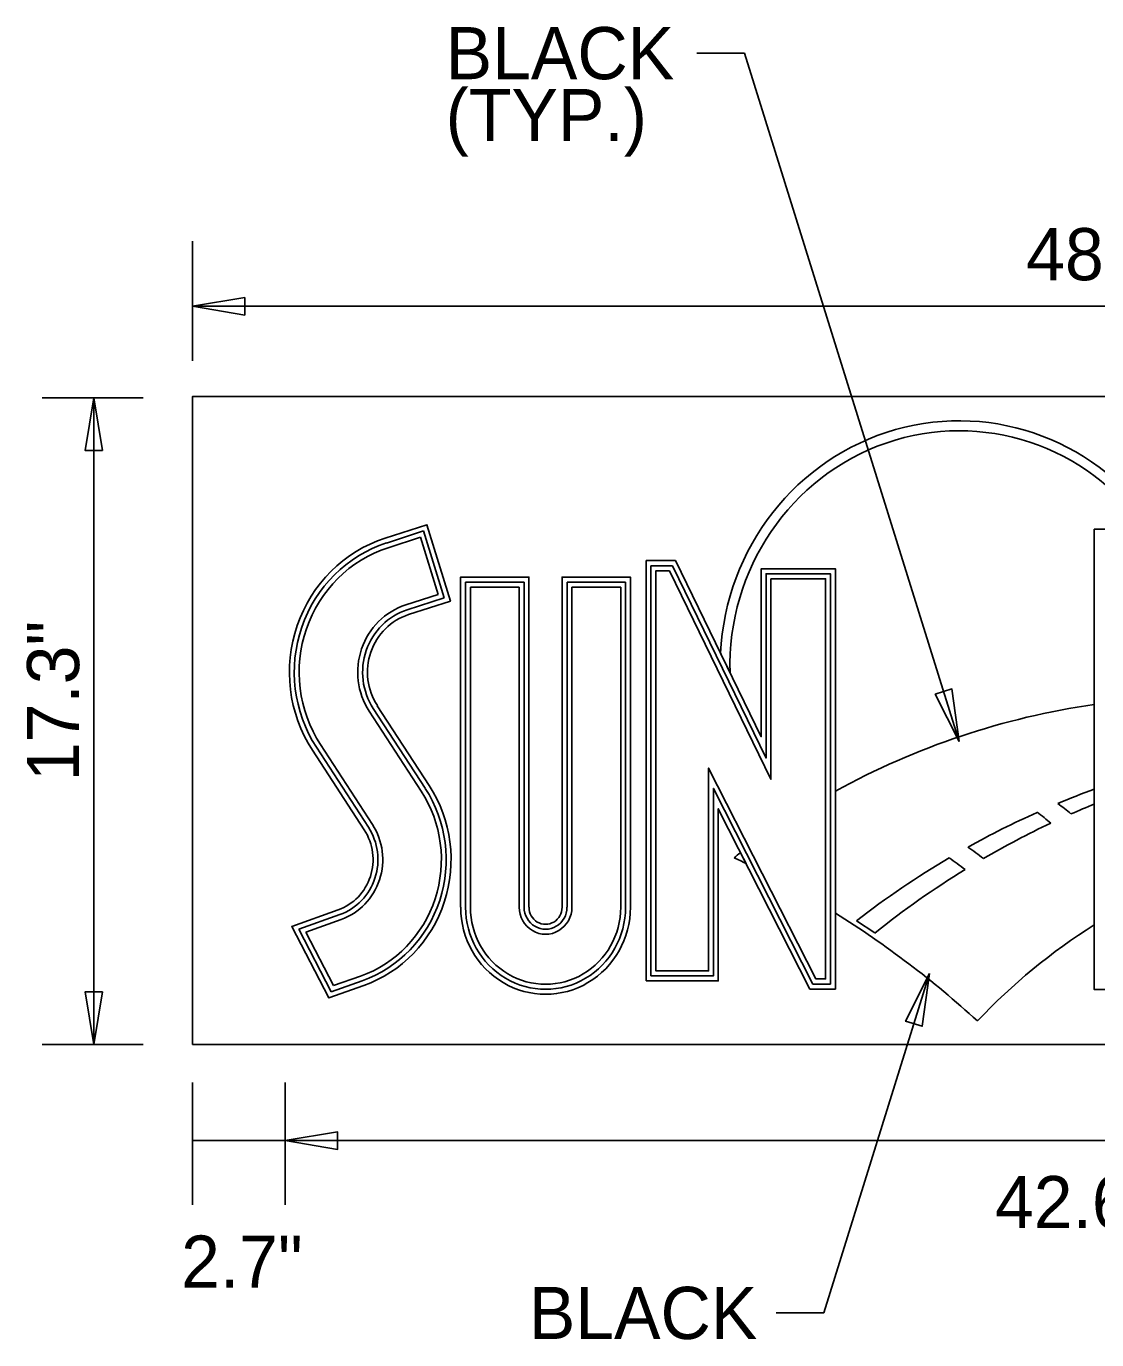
# Model space of a CAD drawing. Extents: x 10268197 to 10268738, y 2141503 to 2142677.
# Drawn here: x 10268673.67 to 10268688.05, y 2142371.53 to 2142389.16 of the extents above; entities that cross this region are included whole.
import ezdxf

# ---------------------------------------------------------------- set-up
doc = ezdxf.new("R2010")
doc.units = 0
for name, color, linetype in [('1', 7, 'Continuous'), ('Default', 7, 'Continuous'), ('GSDims', 7, 'Continuous')]:
    doc.layers.add(name, color=color, linetype=linetype)

msp = doc.modelspace()

# ---------------------------------------------------------------- linework, layer by layer
at = {"layer": '1'}
for p, q in [((10268682.678, 2142388.804), (10268683.317, 2142388.804)), ((10268686.203, 2142379.56), (10268683.317, 2142388.804)), ((10268685.804, 2142376.445), (10268684.382, 2142371.89)), ((10268699.488, 2142375.495), (10268675.901, 2142375.495)), ((10268683.743, 2142371.89), (10268684.382, 2142371.89))]:
    msp.add_line(p, q, dxfattribs=at)
at = {"layer": 'Default'}
for p, q in [((10268678.51, 2142382.227), (10268679.008, 2142382.389)), ((10268678.53, 2142382.163), (10268678.966, 2142382.304)), ((10268678.53, 2142382.163), (10268678.966, 2142382.304)), ((10268678.966, 2142382.304), (10268679.202, 2142381.536)), ((10268678.966, 2142382.304), (10268679.202, 2142381.536)), ((10268679.008, 2142382.389), (10268679.285, 2142381.492)), ((10268681.996, 2142381.99), (10268681.996, 2142376.347)), ((10268682.062, 2142376.414), (10268682.062, 2142381.922)), ((10268679.571, 2142377.336), (10268679.571, 2142381.703)), ((10268679.571, 2142381.703), (10268680.357, 2142381.703)), ((10268680.357, 2142381.703), (10268680.357, 2142377.337)), ((10268680.934, 2142377.337), (10268680.934, 2142381.703)), ((10268680.934, 2142381.703), (10268681.72, 2142381.703)), ((10268681.72, 2142381.703), (10268681.72, 2142377.336)), ((10268682.128, 2142381.855), (10268682.128, 2142376.481)), ((10268682.309, 2142381.855), (10268682.128, 2142381.855)), ((10268683.674, 2142379.056), (10268682.309, 2142381.855)), ((10268683.674, 2142381.748), (10268683.674, 2142379.056)), ((10268684.408, 2142381.748), (10268683.674, 2142381.748)), ((10268684.408, 2142376.374), (10268684.408, 2142381.748)), ((10268679.202, 2142381.536), (10268678.767, 2142381.395)), ((10268679.202, 2142381.536), (10268678.767, 2142381.395)), ((10268679.636, 2142377.337), (10268679.636, 2142381.636)), ((10268679.636, 2142381.636), (10268680.292, 2142381.636)), ((10268679.636, 2142377.337), (10268679.636, 2142381.636)), ((10268679.636, 2142381.636), (10268680.292, 2142381.636)), ((10268680.292, 2142381.636), (10268680.292, 2142377.337)), ((10268680.292, 2142381.636), (10268680.292, 2142377.337)), ((10268680.999, 2142377.337), (10268680.999, 2142381.636)), ((10268680.999, 2142381.636), (10268681.655, 2142381.636)), ((10268680.999, 2142377.337), (10268680.999, 2142381.636)), ((10268680.999, 2142381.636), (10268681.655, 2142381.636)), ((10268681.655, 2142381.636), (10268681.655, 2142377.337)), ((10268681.655, 2142381.636), (10268681.655, 2142377.337)), ((10268679.285, 2142381.492), (10268678.787, 2142381.331)), ((10268682.996, 2142380.747), (10268683.124, 2142380.484)), ((10268678.277, 2142379.969), (10268678.974, 2142378.896)), ((10268678.277, 2142379.969), (10268678.974, 2142378.896)), ((10268678.332, 2142380.006), (10268679.029, 2142378.934)), ((10268679.084, 2142378.971), (10268678.386, 2142380.043)), ((10268688.017, 2142378.923), (10268688.017, 2142380.059)), ((10268677.514, 2142379.447), (10268678.211, 2142378.375)), ((10268678.266, 2142378.412), (10268677.568, 2142379.484)), ((10268678.32, 2142378.449), (10268677.623, 2142379.521)), ((10268678.32, 2142378.449), (10268677.623, 2142379.521)), ((10268682.835, 2142376.481), (10268682.835, 2142379.205)), ((10268682.835, 2142379.205), (10268684.278, 2142376.374)), ((10268684.539, 2142378.896), (10268684.539, 2142377.259)), ((10268688.017, 2142377.099), (10268688.017, 2142378.722)), ((10268683.34, 2142377.925), (10268683.266, 2142378.069)), ((10268677.331, 2142377.042), (10268677.881, 2142377.238)), ((10268677.425, 2142377.004), (10268677.902, 2142377.174)), ((10268677.425, 2142377.004), (10268677.902, 2142377.174)), ((10268685.07, 2142376.991), (10268684.823, 2142377.156)), ((10268677.768, 2142376.202), (10268677.331, 2142377.042)), ((10268677.799, 2142376.284), (10268677.425, 2142377.004)), ((10268677.799, 2142376.284), (10268677.425, 2142377.004)), ((10268678.161, 2142376.413), (10268677.799, 2142376.284)), ((10268678.161, 2142376.413), (10268677.799, 2142376.284)), ((10268682.128, 2142376.481), (10268682.835, 2142376.481)), ((10268678.182, 2142376.349), (10268677.768, 2142376.202)), ((10268684.278, 2142376.374), (10268684.408, 2142376.374)), ((10268699.488, 2142375.495), (10268675.901, 2142375.495))]:
    msp.add_line(p, q, dxfattribs=at)
for points in [[(10268675.901, 2142375.495), (10268675.901, 2142384.193), (10268699.488, 2142384.193), (10268699.488, 2142375.495)], [(10268678.806, 2142381.267), (10268679.367, 2142381.448), (10268679.051, 2142382.473), (10268678.491, 2142382.292)], [(10268689.118, 2142382.412), (10268688.017, 2142382.412), (10268688.017, 2142376.232), (10268689.118, 2142376.232), (10268689.118, 2142378.639)], [(10268681.996, 2142376.347), (10268682.966, 2142376.347), (10268682.966, 2142378.658), (10268684.198, 2142376.239), (10268684.539, 2142376.239), (10268684.539, 2142381.882), (10268683.543, 2142381.882), (10268683.543, 2142379.625), (10268682.39, 2142381.99), (10268681.996, 2142381.99)], [(10268682.062, 2142381.922), (10268682.349, 2142381.922), (10268683.608, 2142379.34), (10268683.608, 2142381.815), (10268684.473, 2142381.815), (10268684.473, 2142376.306), (10268684.238, 2142376.306), (10268682.901, 2142378.931), (10268682.901, 2142376.414), (10268682.062, 2142376.414)], [(10268680.423, 2142377.337), (10268680.423, 2142381.77), (10268679.505, 2142381.77), (10268679.505, 2142377.337)], [(10268681.786, 2142377.337), (10268681.786, 2142381.77), (10268680.868, 2142381.77), (10268680.868, 2142377.337)], [(10268677.859, 2142377.301), (10268677.237, 2142377.079), (10268677.736, 2142376.119), (10268678.204, 2142376.286)]]:
    msp.add_lwpolyline(points, dxfattribs=at)
msp.add_lwpolyline([(10268683.674, 2142381.748), (10268683.674, 2142379.056), (10268682.309, 2142381.855), (10268682.128, 2142381.855), (10268682.128, 2142376.481), (10268682.835, 2142376.481), (10268682.835, 2142379.205), (10268684.278, 2142376.374), (10268684.408, 2142376.374), (10268684.408, 2142381.748)], close=True, dxfattribs=at)
for centre, major_axis, ratio, start_param, end_param in [((10268686.203, 2142380.578), (0, 3.29), 0.97582, 5.303349, 7.802858), ((10268686.203, 2142380.578), (0, 3.29), 0.97582, 5.303349, 7.802858), ((10268686.203, 2142380.578), (0, 3.156), 0.97582, 5.332201, 7.884008), ((10268686.203, 2142380.578), (0, 3.156), 0.97582, 5.332201, 7.884008), ((10268679.045, 2142380.493), (0, 1.886), 0.97582, 0.306207, 2.15869), ((10268679.045, 2142380.493), (0, 1.819), 0.97582, 0.306207, 2.15869), ((10268679.045, 2142380.493), (0, 1.752), 0.975477, 0.305879, 2.158799), ((10268679.045, 2142380.493), (0, 1.752), 0.975477, 0.305879, 2.158799), ((10268679.045, 2142380.493), (0, 0.946), 0.975477, 0.305879, 2.158799), ((10268679.045, 2142380.493), (0, 0.946), 0.975477, 0.305879, 2.158799), ((10268679.045, 2142380.493), (0, 0.878), 0.97582, 0.306207, 2.15869), ((10268679.045, 2142380.493), (0, 0.811), 0.97582, 0.306207, 2.15869), ((10268686.203, 2142380.577), (0, -3.156), 0.97582, 4.712389, 4.712389), ((10268689.453, 2142369.502), (0, 10.658), 0.97582, 0.138501, 0.492135), ((10268689.453, 2142369.502), (0, 10.658), 0.97582, 0.138501, 0.492135), ((10268677.63, 2142377.977), (0, -1.657), 0.975477, 0.334737, 2.158799), ((10268677.63, 2142377.977), (0, -1.657), 0.975477, 0.334737, 2.158799), ((10268677.629, 2142377.977), (0, 1.724), 0.97582, 3.476656, 5.300276), ((10268677.629, 2142377.977), (0, 1.791), 0.97582, 3.476656, 5.300276), ((10268692.076, 2142367.544), (0, -12.098), 0.987081, 3.48834, 3.532255), ((10268677.555, 2142365.833), (0, 16.388), 0.986504, 5.604488, 5.618403), ((10268692.471, 2142367.497), (0, -12.098), 0.987081, 3.5238, 3.552221), ((10268692.076, 2142367.544), (0, -12.098), 0.987081, 3.557551, 3.644446), ((10268677.555, 2142365.833), (0, 16.12), 0.986688, 5.613012, 5.627647), ((10268677.63, 2142377.977), (0, 0.716), 0.97582, 3.476661, 5.300276), ((10268677.63, 2142377.977), (0, 0.783), 0.97582, 3.476661, 5.300276), ((10268677.63, 2142377.977), (0, -0.85), 0.975477, 0.334742, 2.158799), ((10268677.63, 2142377.977), (0, -0.85), 0.975477, 0.334742, 2.158799), ((10268692.471, 2142367.497), (0, -12.098), 0.987081, 3.577057, 3.66248), ((10268689.453, 2142369.502), (0, 10.658), 0.97582, 0.637151, 0.647654), ((10268689.453, 2142369.502), (0, 10.658), 0.97582, 0.637152, 0.647654), ((10268677.61, 2142365.619), (0, 13.634), 0.97582, 5.837989, 5.851358), ((10268677.61, 2142365.619), (0, 13.634), 0.97582, 5.837989, 5.851358), ((10268692.076, 2142367.544), (0, -12.098), 0.987081, 3.668845, 3.794286), ((10268677.555, 2142365.833), (0, 14.911), 0.987597, 5.648885, 5.666846), ((10268677.555, 2142365.833), (0, 15.179), 0.987382, 5.641271, 5.658477), ((10268692.471, 2142367.497), (0, -12.098), 0.987081, 3.686493, 3.810103), ((10268680.646, 2142377.336), (0, 1.168), 0.97582, 1.570446, 4.71274), ((10268680.646, 2142377.336), (0, 1.101), 0.97582, 1.570446, 4.71274), ((10268680.646, 2142377.337), (0, -1.035), 0.975477, 4.712389, 7.853982), ((10268680.646, 2142377.337), (0, -1.035), 0.975477, 4.712389, 7.853982), ((10268680.646, 2142377.337), (0, -0.363), 0.975477, 4.712389, 7.853982), ((10268680.646, 2142377.337), (0, -0.363), 0.975477, 4.712389, 7.853982), ((10268680.646, 2142377.336), (0, 0.295), 0.97582, 1.570446, 4.71274), ((10268680.646, 2142377.336), (0, 0.228), 0.97582, 1.570446, 4.71274), ((10268677.61, 2142365.619), (0, 13.634), 0.97582, 5.556667, 5.735414), ((10268677.61, 2142365.619), (0, 13.634), 0.97582, 5.556667, 5.735414), ((10268692.169, 2142370.305), (0, -7.986), 0.98893, 3.695067, 3.951695), ((10268692.169, 2142370.305), (0, -7.986), 0.98893, 3.695067, 3.951695)]:
    msp.add_ellipse(centre, major_axis=major_axis, ratio=ratio, start_param=start_param, end_param=end_param, dxfattribs=at)
at = {"layer": 'GSDims'}
for p, q in [((10268675.901, 2142384.671), (10268675.901, 2142386.279)), ((10268675.901, 2142385.405), (10268699.488, 2142385.405)), ((10268675.241, 2142384.176), (10268673.885, 2142384.176)), ((10268674.577, 2142375.495), (10268674.577, 2142384.176)), ((10268675.241, 2142375.495), (10268673.885, 2142375.495)), ((10268675.901, 2142374.982), (10268675.901, 2142373.342)), ((10268677.148, 2142374.982), (10268677.148, 2142373.342)), ((10268675.901, 2142374.203), (10268677.148, 2142374.203)), ((10268677.148, 2142374.203), (10268698.271, 2142374.203))]:
    msp.add_line(p, q, dxfattribs=at)
for points in [[(10268675.901, 2142385.405), (10268676.605, 2142385.288), (10268676.605, 2142385.522)], [(10268674.577, 2142384.176), (10268674.694, 2142383.471), (10268674.459, 2142383.471)], [(10268686.203, 2142379.56), (10268686.105, 2142380.267), (10268685.881, 2142380.197)], [(10268685.804, 2142376.445), (10268685.706, 2142375.738), (10268685.482, 2142375.807)], [(10268674.577, 2142375.495), (10268674.694, 2142376.199), (10268674.459, 2142376.199)], [(10268677.148, 2142374.203), (10268677.852, 2142374.32), (10268677.852, 2142374.085)]]:
    msp.add_lwpolyline(points, close=True, dxfattribs=at)

# ---------------------------------------------------------------- texts
at = {"layer": '1'}
for s, p in [('BLACK', (10268679.304, 2142388.454)), ('(TYP.)', (10268679.304, 2142387.623)), ('48"', (10268687.103, 2142385.755)), ('42.6"', (10268686.684, 2142373.028)), ('2.7"', (10268675.75, 2142372.229)), ('BLACK', (10268680.421, 2142371.54))]:
    msp.add_text(s, height=0.7, dxfattribs=at).set_placement(p)
msp.add_text('17.3"', height=0.7, rotation=90, dxfattribs=at).set_placement((10268674.38, 2142379.029))

doc.saveas('drawing.dxf')
